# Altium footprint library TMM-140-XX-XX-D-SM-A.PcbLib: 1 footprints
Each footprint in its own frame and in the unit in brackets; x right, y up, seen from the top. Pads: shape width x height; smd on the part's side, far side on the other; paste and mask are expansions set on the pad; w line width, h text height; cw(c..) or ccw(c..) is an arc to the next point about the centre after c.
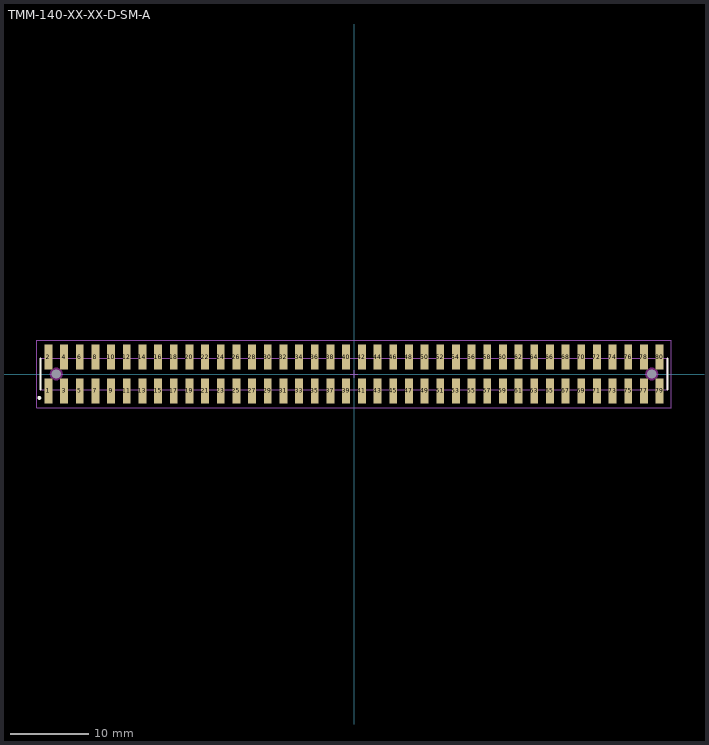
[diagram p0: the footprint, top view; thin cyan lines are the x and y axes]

## TMM-140-XX-XX-D-SM-A [mm] "2.00mm pitch, 80 pin, terminal strip; double row, w/alignment pins, SMT"
height 2.77
pads (82):
  rect 1x3.2 smd mask+0: 1(-39,-2.15) 2(-39,2.15) 3(-37,-2.15) 4(-37,2.15) 5(-35,-2.15) 6(-35,2.15) 7(-33,-2.15) 8(-33,2.15) 9(-31,-2.15) 10(-31,2.15) 11(-29,-2.15) 12(-29,2.15) 13(-27,-2.15) 14(-27,2.15) 15(-25,-2.15) 16(-25,2.15) 17(-23,-2.15) 18(-23,2.15) 19(-21,-2.15) 20(-21,2.15) 21(-19,-2.15) 22(-19,2.15) 23(-17,-2.15) 24(-17,2.15) 25(-15,-2.15) 26(-15,2.15) 27(-13,-2.15) 28(-13,2.15) 29(-11,-2.15) 30(-11,2.15) 31(-9,-2.15) 32(-9,2.15) 33(-7,-2.15) 34(-7,2.15) 35(-5,-2.15) 36(-5,2.15) 37(-3,-2.15) 38(-3,2.15) 39(-1,-2.15) 40(-1,2.15) 41(1,-2.15) 42(1,2.15) 43(3,-2.15) 44(3,2.15) 45(5,-2.15) 46(5,2.15) 47(7,-2.15) 48(7,2.15) 49(9,-2.15) 50(9,2.15) 51(11,-2.15) 52(11,2.15) 53(13,-2.15) 54(13,2.15) 55(15,-2.15) 56(15,2.15) 57(17,-2.15) 58(17,2.15) 59(19,-2.15) 60(19,2.15) 61(21,-2.15) 62(21,2.15) 63(23,-2.15) 64(23,2.15) 65(25,-2.15) 66(25,2.15) 67(27,-2.15) 68(27,2.15) 69(29,-2.15) 70(29,2.15) 71(31,-2.15) 72(31,2.15) 73(33,-2.15) 74(33,2.15) 75(35,-2.15) 76(35,2.15) 77(37,-2.15) 78(37,2.15) 79(39,-2.15) 80(39,2.15)
  round 1 hole 1.2 unplated mask+0: 81(-38,0) 82(38,0)
Top Overlay:
  circle w0.25: c-40.15,-3.05 r0.125
  lines w0.2: -40,-2 -40,2 ; 40,-2 40,2
Keep-Out Layer:
  pour cut-out: 38.807,0 38.779,0.209 38.699,0.403 38.57,0.571 38.403,0.699 38.209,0.779 38,0.807 37.791,0.779 37.596,0.699 37.429,0.571 37.301,0.403 37.22,0.209 37.193,0 37.22,-0.209 37.301,-0.403 37.429,-0.571 37.596,-0.699 37.791,-0.779 38,-0.807 38.209,-0.779 38.403,-0.699 38.57,-0.571 38.699,-0.403 38.779,-0.209
  pour cut-out: -37.193,0 -37.22,0.209 -37.301,0.403 -37.429,0.571 -37.596,0.699 -37.791,0.779 -38,0.807 -38.209,0.779 -38.403,0.699 -38.57,0.571 -38.699,0.403 -38.779,0.209 -38.807,0 -38.779,-0.209 -38.699,-0.403 -38.57,-0.571 -38.403,-0.699 -38.209,-0.779 -38,-0.807 -37.791,-0.779 -37.596,-0.699 -37.429,-0.571 -37.301,-0.403 -37.22,-0.209
Mechanical 12:
  lines w0.001: -40,-2 -40,2 40,2 40,-2 -40,-2
Mechanical 13:
  lines w0.1: -40,-2 -40,2 40,2 40,-2 -40,-2
  text ".Designator" at 0,-0.127 h1.52
Mechanical 15:
  lines w0.05: -0.5,0 0.5,0 ; 0,-0.5 0,0.5 ; -40.5,-4.3 -40.5,4.3 40.5,4.3 40.5,-4.3 -40.5,-4.3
